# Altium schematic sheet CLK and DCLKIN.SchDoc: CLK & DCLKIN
size 431 x 279 mm; Date: Not shown in title block; ApprovedBy: Not shown in title block; CheckedBy: Not shown in title block; Author: Not shown in title block; CompanyName: Not shown in title block; Engineer: Not shown in title block; Organization: Not shown in title block; Address1: Not shown in title block; Address2: Not shown in title block; Address3: Not shown in title block; Address4: Not shown in title block; DocumentNumber: 1; Revision: Use project parameter SCH_Rev; SheetNumber: 8; SheetTotal: 15; PageSetup: Record=PageOptions¦CenterHorizontal=True¦CenterVertical=True¦PrintScale=1.00¦XCorrection=1.00¦YCorrection=1.00¦PrintKind=0¦BorderSize=5000000¦LeftOffset=0¦BottomOffset=0¦Orientation=2¦PaperLength=1000¦PaperWidth=1000¦Scale=100¦PaperSource=15¦PrintQuality=600¦MediaType=1¦DitherType=10¦PaperKind=Letter¦PrintScaleMode=1
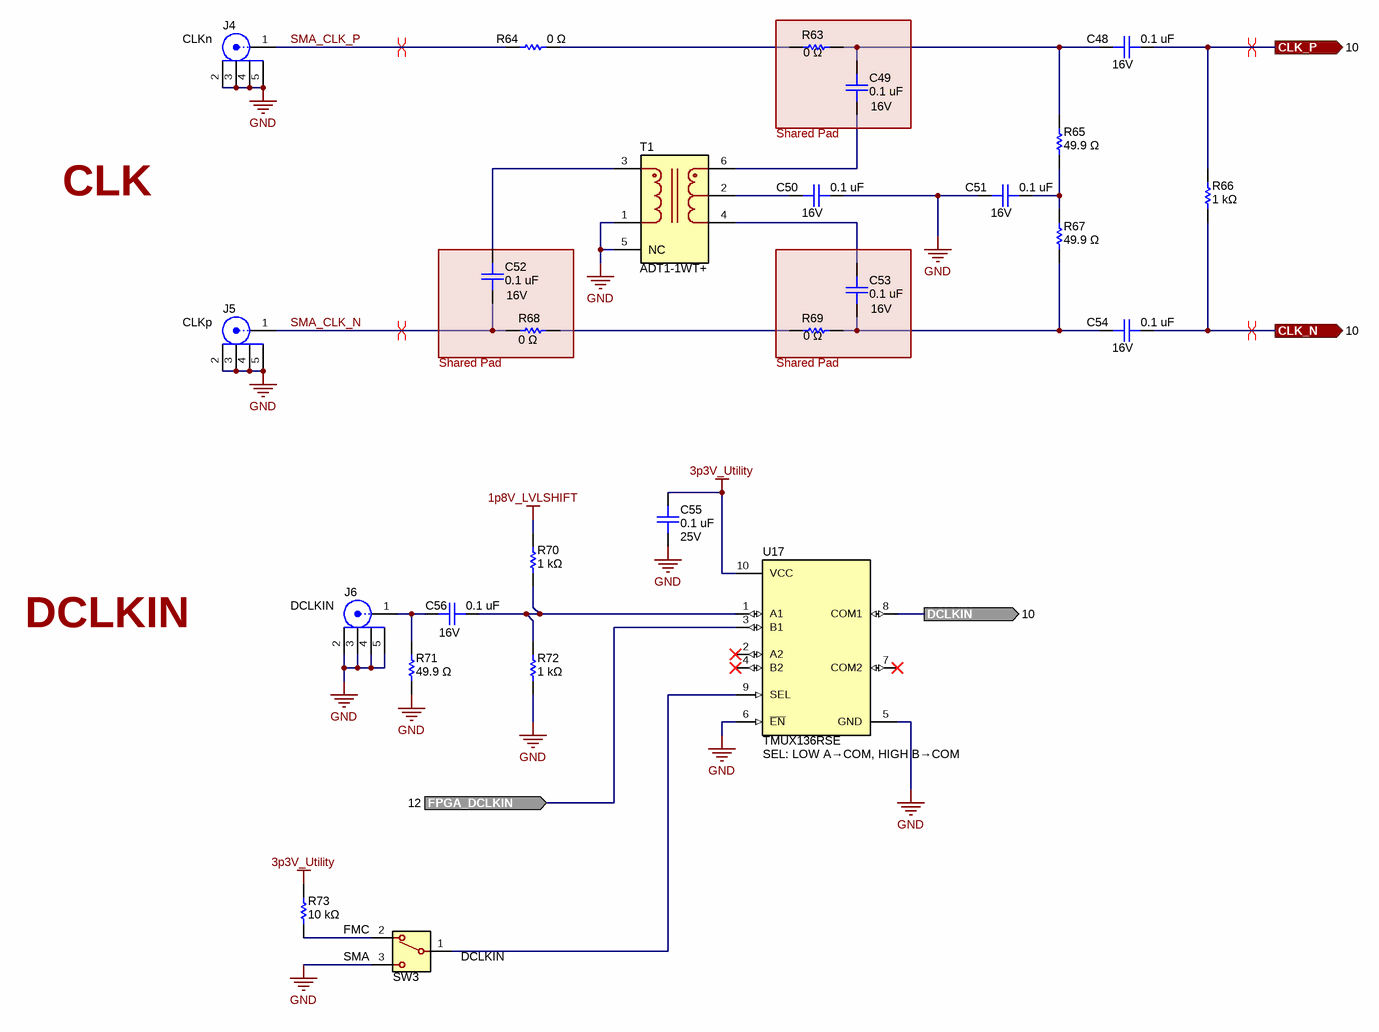
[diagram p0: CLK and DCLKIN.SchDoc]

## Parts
(Parts that share a designator on the sheet are numbered #1, #2 ... from top to bottom, then left to right.)
?#1  Shared Pad  (graphical)
?#2  Shared Pad  (graphical)
?#3  Shared Pad  (graphical)
C48  value 0.1 uF  Voltage - Rated: 16V  [0201_cap]  (hidden comment: GRM033Z71C104ME14D)
C49  value 0.1 uF  Voltage - Rated: 16V  [0201_cap]  (hidden comment: GRM033Z71C104ME14D)
C50  value 0.1 uF  Voltage - Rated: 16V  [0201_cap]  (hidden comment: GRM033Z71C104ME14D)
C51  value 0.1 uF  Voltage - Rated: 16V  [0201_cap]  (hidden comment: GRM033Z71C104ME14D)
C52  value 0.1 uF  Voltage - Rated: 16V  [0201_cap]  (hidden comment: GRM033Z71C104ME14D)
C53  value 0.1 uF  Voltage - Rated: 16V  [0201_cap]  (hidden comment: GRM033Z71C104ME14D)
C54  value 0.1 uF  Voltage - Rated: 16V  [0201_cap]  (hidden comment: GRM033Z71C104ME14D)
C55  value 0.1 uF  Voltage - Rated: 25V  [0402L_cap]  (hidden comment: GRT155R71E104KE01J)
C56  value 0.1 uF  Voltage - Rated: 16V  [0201_cap]  (hidden comment: GRM033Z71C104ME14D)
J4  Text1: CLKn  [FP-132134-15_CONN_SMA_JACK-MFG]  (hidden comment: 132134-15)
J5  Text1: CLKp  [FP-132134-15_CONN_SMA_JACK-MFG]  (hidden comment: 132134-15)
J6  Text1: DCLKIN  [FP-132134-15_CONN_SMA_JACK-MFG]  (hidden comment: 132134-15)
R63  value 0 Ω  [0201]  (hidden comment: ERJ-1GN0R00C)
R64  value 0 Ω  [0201]  (hidden comment: ERJ-1GN0R00C)
R65  value 49.9 Ω  [0201]  (hidden comment: ERJ-1GNF49R9C)
R66  value 1 kΩ  [0201]  (hidden comment: ERJ-1GNF1001C)
R67  value 49.9 Ω  [0201]  (hidden comment: ERJ-1GNF49R9C)
R68  value 0 Ω  [0201]  (hidden comment: ERJ-1GN0R00C)
R69  value 0 Ω  [0201]  (hidden comment: ERJ-1GN0R00C)
R70  value 1 kΩ  [0201]  (hidden comment: ERJ-1GNF1001C)
R71  value 49.9 Ω  [0201]  (hidden comment: ERJ-1GNF49R9C)
R72  value 1 kΩ  [0201]  (hidden comment: ERJ-1GNF1001C)
R73  value 10 kΩ  [0402L]  (hidden comment: ERA-2AEB103X)
SW3  Text1: DCLKIN  Text2: FMC  Text3: SMA  [450301014042]  (hidden comment: cmp00353)
T1  ADT1-1WT+  [CD542]
U17  TMUX136RSE  Text1: SEL: LOW A→COM, HIGH B→COM  [RSE0010A]

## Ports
CLK_N (out, see 10), CLK_P (out, see 10), DCLKIN (out, see 10), FPGA_DCLKIN (in, see 12)

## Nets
1p8V_LVLSHIFT: R70.2
3p3V_Utility: C55.2 R73.2 U17.10(VCC)
GND: C50.2 C51.1 C55.1 J4.2 J4.3 J4.4 J4.5 J5.2 J5.3 J5.4 J5.5 J6.2 J6.3 J6.4 J6.5 R71.1 R72.1 SW3.3 T1.1(PRIMARY) T1.5(NC) U17.5(GND) U17.6(~{EN})
CLK_N: C54.2 R66.1 ; port CLK_N
CLK_P: C48.2 R66.2 ; port CLK_P
DCLKIN: U17.8(COM1) ; port DCLKIN
FPGA_DCLKIN: U17.3(B1) ; port FPGA_DCLKIN
SMA_CLK_N: C52.2 J5.1 R68.1
SMA_CLK_P: J4.1 R64.1
NetC48_1: C48.1 C49.2 R63.2 R65.2
NetC49_1: C49.1 T1.6(SECONDARY_DOT)
NetC50_1: C50.1 T1.2(SECONDARY_CT)
NetC51_2: C51.2 R65.1 R67.2
NetC52_1: C52.1 T1.3(PRIMARY_DOT)
NetC53_1: C53.1 C54.1 R67.1 R69.2
NetC53_2: C53.2 T1.4(SECONDARY)
NetC56_1: C56.1 R70.1 R72.2 U17.1(A1)
NetC56_2: C56.2 J6.1 R71.2
NetR63_1: R63.1 R64.2
NetR68_2: R68.2 R69.1
NetR73_1: R73.1 SW3.2(COMM)
NetSW3_1: SW3.1 U17.9(SEL)

Not connected (* = marked no-connect by the designer): U17 2(A2)* 4(B2)* 7(COM2)*

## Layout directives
differential pair; net class DiffPairIN: CLK_N, CLK_P
differential pair: SMA_CLK_N, SMA_CLK_P

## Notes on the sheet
- CLK
- DCLKIN

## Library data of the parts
?#1-?#3 = Swizzle: Schematic notation to show that the pads of two components should be overlapped
C48-C54 C56 = capcc09270: CAP CER 0.1UF 16V X7R 0201; Manufacturer: Murata Electronics; CompType: Capacitor Ceramic; Tolerance: ±20%; SizeX_mm: 0.6; SizeY_mm: 0.3; SizeZ_mm: 0.33
C55 = capcc09401: CAP CER 0.1UF 25V X7R 0402; Manufacturer: Murata; CompType: Capacitor Ceramic; Tolerance: ±10%; SizeX_mm: 1; SizeY_mm: 0.5; SizeZ_mm: 0.7
J4-J6 = 132134-15: SMA Connector Jack, Female Socket 50Ohm Surface Mount, Through Hole Solder; Manufacturer: Amphenol RF; UniqueID: cmp00028; CompType: RF Connector
R63 R64 R68 R69 = RSMD020101699: RES SMD 0 OHM JUMPER 1/20W 0201; Manufacturer: Panasonic Electronic Components; CompType: Resistor SMD; Power (Watts): 0.05W, 1/20W
R65 R67 R71 = RSMD020100177: RES SMD 49.9 OHM 1% 1/20W 0201; Manufacturer: Panasonic Electronic Components; CompType: Resistor SMD; Power (Watts): 0.05W, 1/20W; Temperature Coefficient: ±200ppm/°C
R66 R70 R72 = RSMD020100143: RES SMD 1K OHM 1% 1/20W 0201; Manufacturer: Panasonic Electronic Components; CompType: Resistor SMD; Power (Watts): 0.05W, 1/20W; Temperature Coefficient: ±200ppm/°C
R73 = RSMD040200315: RES SMD 10K OHM 0.1% 1/16W 0402; Manufacturer: Panasonic Electronic Components; CompType: Resistor SMD; Power (Watts): 0.063W, 1/16W; Temperature Coefficient: ±25ppm/°C; SizeX_mm: 1; SizeY_mm: 0.5; SizeZ_mm: 0.4
SW3 = cmp00353: Switch Slide SPDT 12V, 500mA; Manufacturer: Wurth Elektronik
T1 = ADT1-1WT+: RF Transformer, 75 ohm, 1: 1, 0.4-800MHz, SMT; Manufacturer: Mini-Circuits; AEC Qualified: No; Return Loss: 9.75dB; Insertion Loss: 0.68-2.44dB; SizeZ_mm: 2.84mm
U17 = cmp00385: 1.4-pF on-state capacitance, 5-V, 2:1 (SPDT), 2-channel analog switch with powered-off protection; PartNumber: TMUX136RSER; Manufacturer: Texas Instruments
